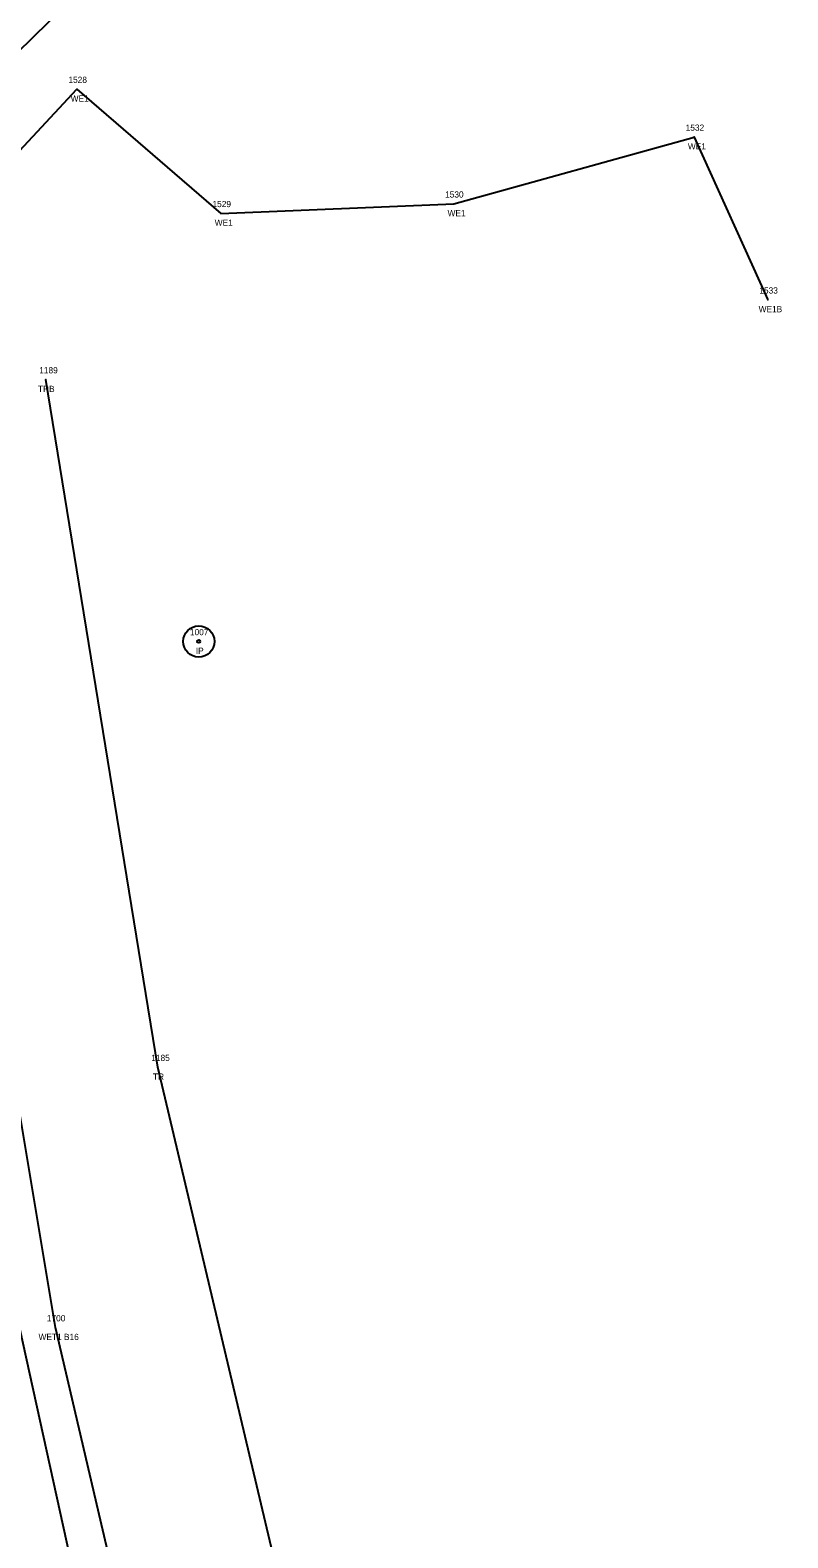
# Model space of a CAD drawing. Extents: x 2521558 to 2524785, y 882711 to 887632.
# Drawn here: x 2523859.8 to 2523981.4, y 884884.6 to 885126.7 of the extents above; entities that cross this region are included whole.
import ezdxf

# ---------------------------------------------------------------- set-up
doc = ezdxf.new("R2010")
doc.units = 0
for name, color, linetype in [('RD_EV_JurisArea', 7, 'Continuous'), ('RD_EX_DV_Prop_txCode', 7, 'Continuous'), ('RD_EX_DV_PropPin', 7, 'Continuous'), ('RD_EX_H2O', 7, 'Continuous'), ('RD_EX_H2O_txCode', 7, 'Continuous'), ('RD_EX_H2O_WetLd_txCode', 7, 'Continuous'), ('RD_EX_VEG', 7, 'Continuous'), ('RD_EX_VEG_txCode', 7, 'Continuous'), ('RD_PD_GR', 7, 'Continuous'), ('RD_SMD_Locator', 7, 'Continuous')]:
    doc.layers.add(name, color=color, linetype=linetype)

msp = doc.modelspace()

# ---------------------------------------------------------------- linework, layer by layer
at = {"layer": 'RD_EV_JurisArea'}
msp.add_lwpolyline([(2523944.86, 884550.08), (2523910.41, 884709.58), (2523888.01, 884815.03), (2523863.93, 884918.37), (2523848.43, 885010.84), (2523837.07, 885095.13), (2523817.82, 885104.47)], dxfattribs=at)
at = {"layer": 'RD_EX_DV_PropPin'}
for radius in [2.5, 0.25]:
    msp.add_circle((2523886.89, 885028.52), radius, dxfattribs=at)
at = {"layer": 'RD_EX_H2O'}
for points in [[(2523582.82, 884766.34), (2523598.11, 884856.98), (2523627.59, 884901.75), (2523623.76, 884928.28), (2523586.58, 884955.43), (2523600.94, 884974.12), (2523633.05, 884997.68), (2523679.17, 885037.05), (2523744.72, 885076.89), (2523769.38, 885099), (2523825.47, 885108.66), (2523825.47, 885108.66), (2523845.24, 885110.83), (2523890.25, 885154.93)], [(2523827.83, 885106), (2523850.3, 885098.92), (2523867.33, 885117.19), (2523890.44, 885097.24), (2523927.79, 885098.78), (2523966.35, 885109.5), (2523978.17, 885083.37)]]:
    msp.add_lwpolyline(points, dxfattribs=at)
at = {"layer": 'RD_EX_VEG'}
msp.add_lwpolyline([(2523998.75, 884575.96), (2523966.17, 884559.06), (2523924.93, 884771.45), (2523880.33, 884960.16), (2523862.36, 885070.56)], dxfattribs=at)
at = {"layer": 'RD_PD_GR'}
msp.add_line((2523833.35, 885030.72), (2523900.02, 884727.97), dxfattribs=at)
at = {"layer": 'RD_SMD_Locator'}
for centre in [(2523867.33, 885117.19), (2523966.35, 885109.5), (2523890.44, 885097.24), (2523927.79, 885098.78), (2523978.17, 885083.37), (2523862.36, 885070.56), (2523880.33, 884960.16), (2523863.93, 884918.37)]:
    msp.add_circle(centre, 0.001, dxfattribs=at)

# ---------------------------------------------------------------- texts
at = {"layer": 'RD_EX_DV_Prop_txCode'}
for s, p in [('1007', (2523885.47, 885029.52)), ('IP', (2523886.42, 885026.52))]:
    msp.add_text(s, height=1, dxfattribs=at).set_placement(p)
at = {"layer": 'RD_EX_H2O_txCode'}
for s, p in [('1528', (2523865.98, 885118.19)), ('WE1', (2523866.34, 885115.19)), ('1532', (2523965.01, 885110.5)), ('WE1', (2523965.37, 885107.5)), ('1530', (2523926.41, 885099.78)), ('1529', (2523889.09, 885098.24)), ('WE1', (2523926.81, 885096.78)), ('WE1', (2523889.45, 885095.24)), ('1533', (2523976.83, 885084.37)), ('WE1B', (2523976.72, 885081.37))]:
    msp.add_text(s, height=1, dxfattribs=at).set_placement(p)
at = {"layer": 'RD_EX_H2O_WetLd_txCode'}
for s, p in [('1700', (2523862.51, 884919.37)), ('WET1 B16', (2523861.18, 884916.37))]:
    msp.add_text(s, height=1, dxfattribs=at).set_placement(p)
at = {"layer": 'RD_EX_VEG_txCode'}
for s, p in [('1189', (2523861.29, 885071.56)), ('TRB', (2523861.09, 885068.56)), ('1185', (2523879.27, 884961.16)), ('TR', (2523879.54, 884958.16))]:
    msp.add_text(s, height=1, dxfattribs=at).set_placement(p)

doc.saveas('drawing.dxf')
